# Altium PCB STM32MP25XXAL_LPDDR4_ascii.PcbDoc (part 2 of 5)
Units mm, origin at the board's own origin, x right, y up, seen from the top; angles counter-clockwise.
Board outline 125 x 95 mm, 6 copper layers (Top Layer, Signal Layer 1, Signal Layer 2, Signal Layer 3, Signal Layer 4, Bottom Layer), stack 1.403 mm thick; 182 components, 297 nets, 1131 pads, 958 vias.
Unrouted connection lines stored in the file: 5.
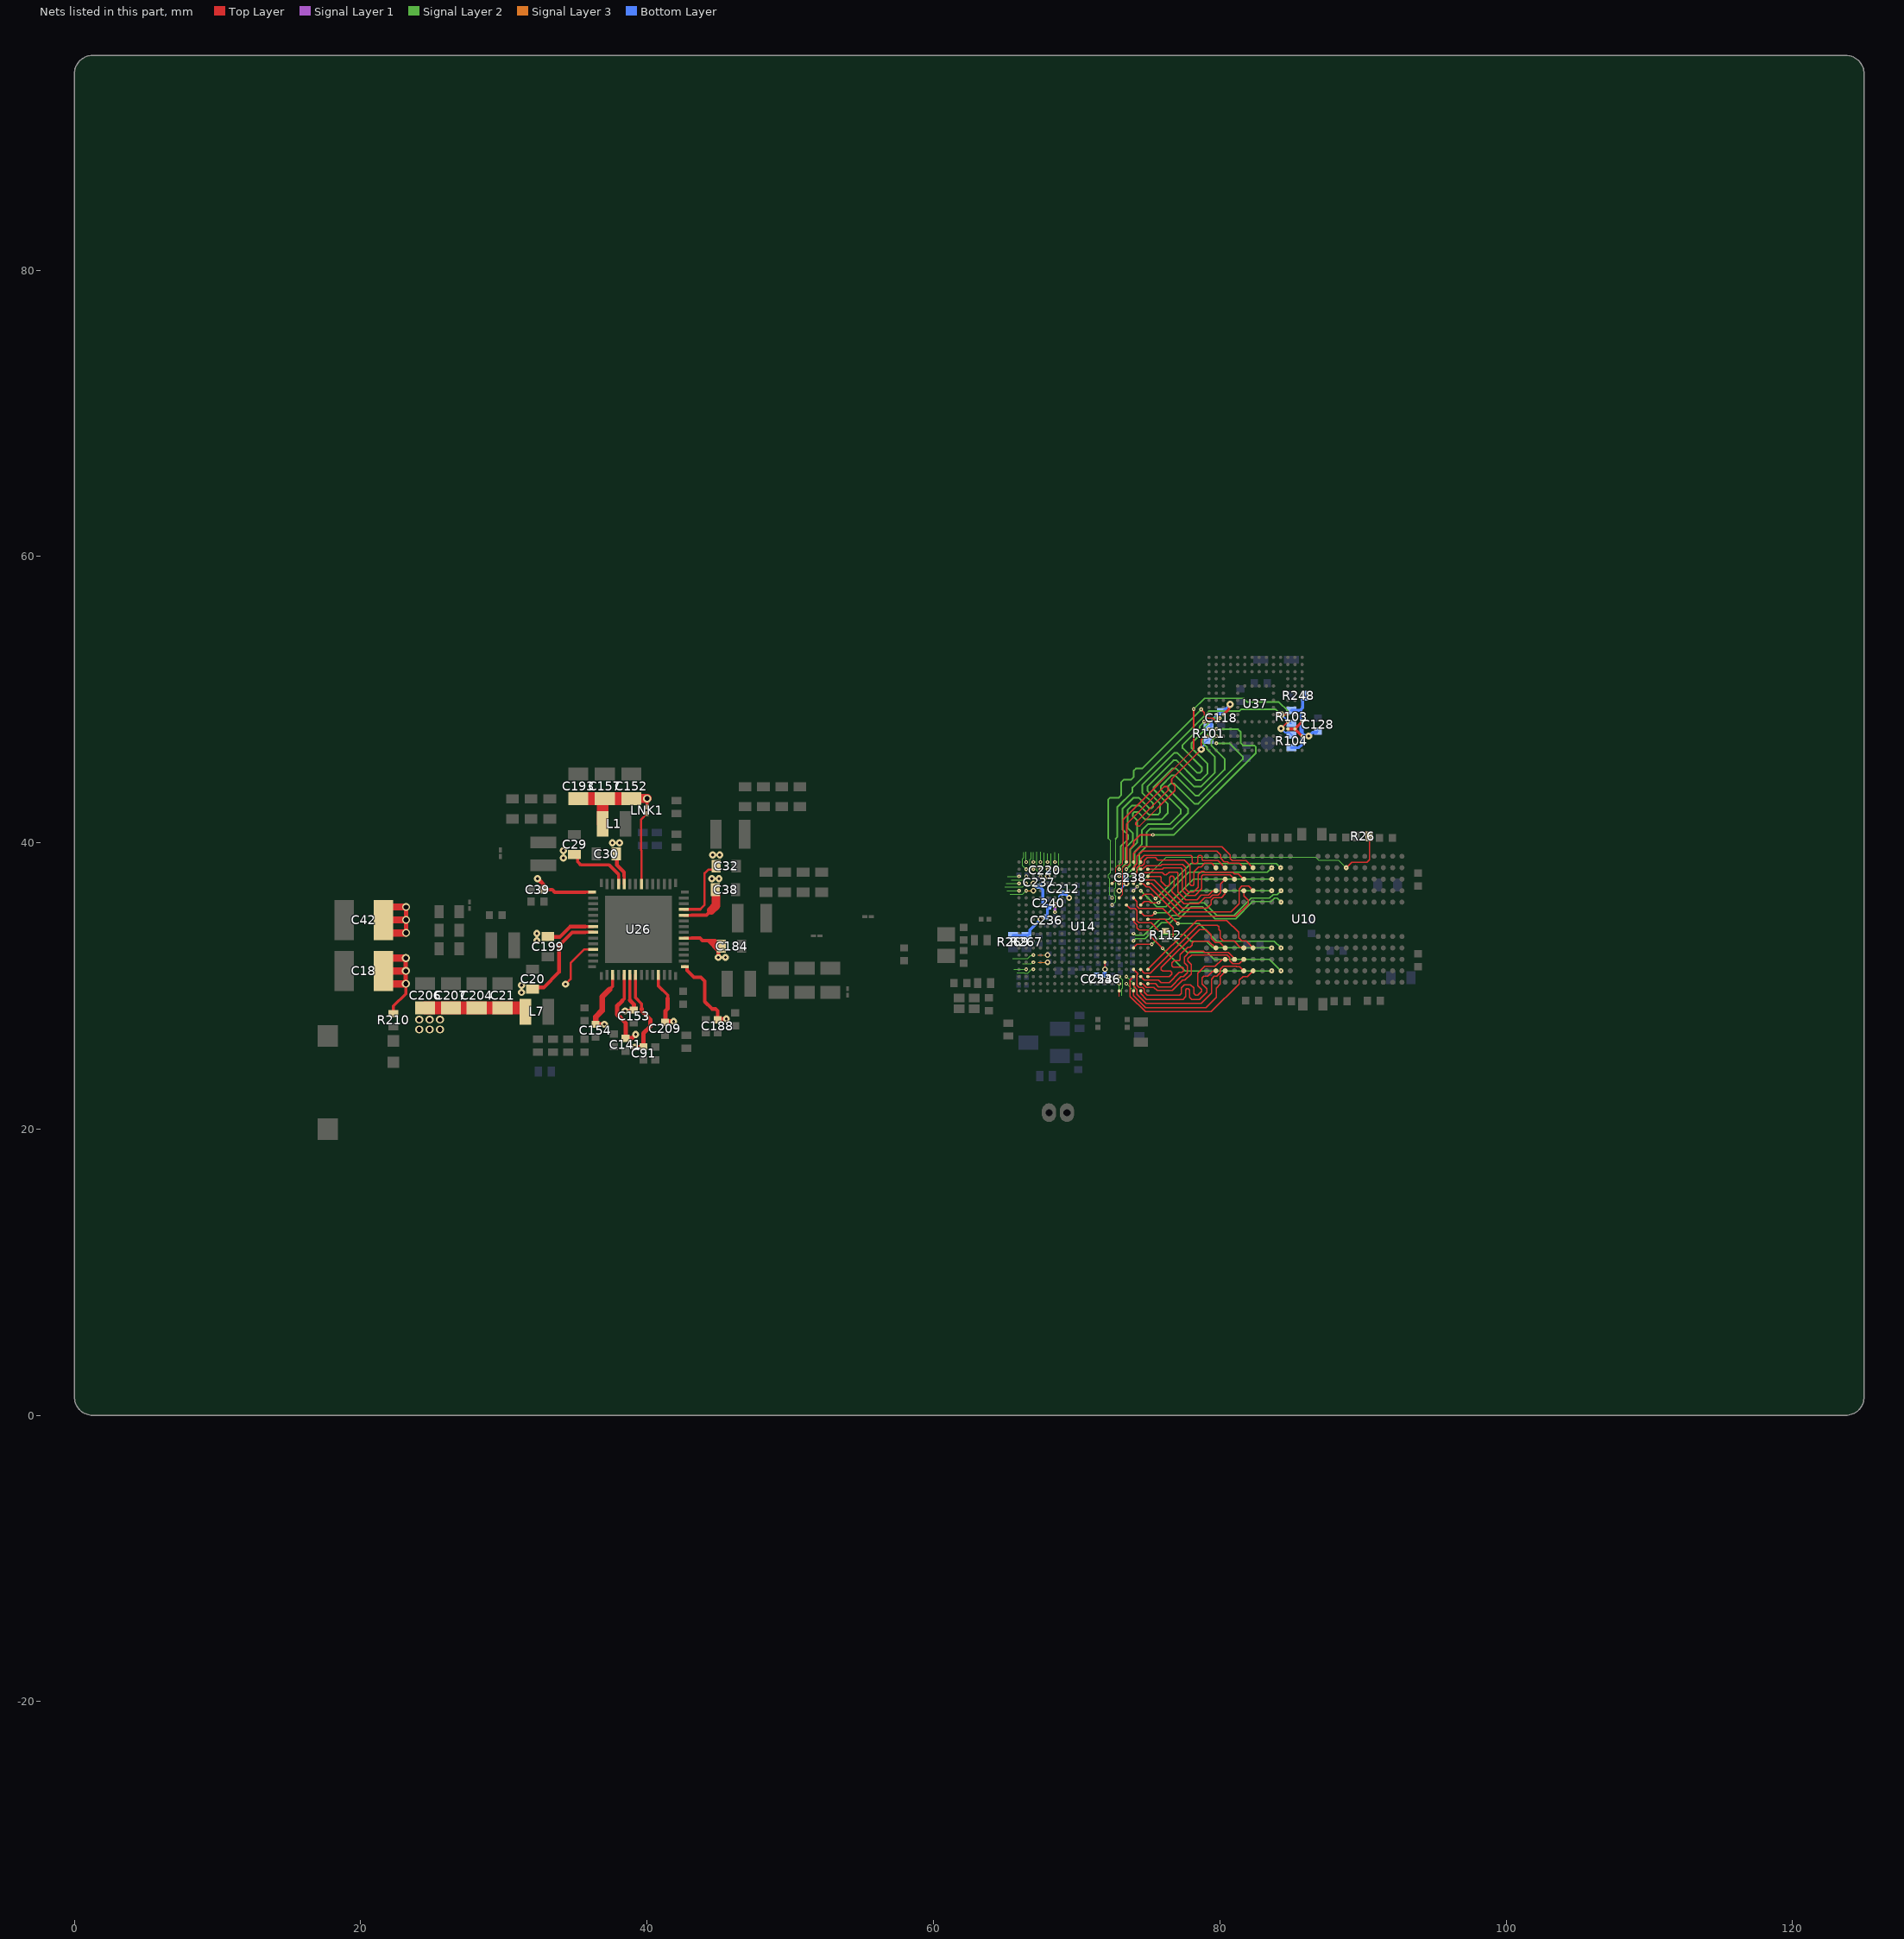
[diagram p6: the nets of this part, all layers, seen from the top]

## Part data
B2: library part MCD-03492, "Switch tactile, SPST-NO, 50mA, 12V, 6x3.8mm"
C1 C2 C3 C4 C5 C15 C214 C250 C260: library part MCD-02377, "Capacitor, MLCC, 1uF, 6.3V, X5R, +/-20%, 0201, T=0,3mm"
C9 C52 C53 C54 C55 C56 C57 C58 C59 C60 C61 C64 C65 C66 C67 C68 C87 C118 C130: library part MCD-00006, "Capacitor, MLCC, 100nF, 16V, X7R, +/-10%, 0402, T=0.5mm"
C14: library part MCD-01823, "Capacitor, MLCC, 2.2uF, 6V3, X5R,+/-10%, 0402, T=0.5mm"
C16 C17 C201 C210 C212 C215 C219 C220 C234 C236 C237 C238 C240 C244 C246 C248 C251 C253: library part MCD-01535, "Capacitor, MLCC,100nF, 10V, X5R, +/-10%, 0201, T=0.3mm"
C18 C42: library part MCD-01796, "Capacitor, Tantalum, 100uF, 6V3, 40mR, +/-20%,  Type_B (3528 metric), T=1.9mm"
C19 C21 C152 C157 C186 C187 C193 C204 C206 C207: library part MCD-03139, "Capacitor, MLCC, 22uF, 10V, X5R, +/-20%, 0805, T=1,25mm"
C20 C29 C30 C32 C38 C184 C199: library part MCD-00099, "Capacitor, MLCC, 10uF, 10V, X5R, +/-10%, 0603, T=0,8mm"
C22 C23 C24 C26 C27 C28 C34 C35 C36 C37 C41 C183 C200 C202: library part MCD-00100, "Capacitor, MLCC, 22uF, 6V3, X5R, +/-20%, 0603, T=0,8mm"
C33: library part MCD-00011, "Capacitor, MLCC, 10nF, 16V, X7R, +/-10%, 0402, T=0.5mm"
C39 C43 C153 C154 C188: library part MCD-00095, "Capacitor, MLCC, 1uF, 25V, X5R, +/-10%, 0402, T=0.5mm"
C40: library part MCD-03140, "Capacitor, MLCC, 10uF, 6.3V, X5R, +/-20%, 0402, T=0.5mm"
C50 C51 C62 C63: library part MCD-01341, "Capacitor, MLCC, 10uF, 6V3, X5R, +/-20%, 0603, T=0.8mm"
C79 C117 C128: library part MCD-02606, "Capacitor, MLCC, 2.2uF, 6.3V, X5R, +/-10%, 0402, T=0.5mm"
C81 C86 C90 C92: library part MCD-00674, "Capacitor, MLCC, 6.8pF, 50V, NPO, +/-0.25pF, 0402, T=0.5mm"
C91 C141 C142 C156 C189 C190 C208 C209 C217: library part MCD-01356, "Capacitor, MLCC, 4.7uF, 6V3, X5R, +/-20%, 0402, T=0.5mm"
C155: library part MCD-02198, "Capacitor, MLCC, 10nF, 50V, X7R, +/-10%, 0402, T=0.5mm"
C175 C177 C191 C192 C194 C195 C196 C197 C203 C205 C211 C213 C283 C284 C287 C289 C299 C300 C304 C306 C307: library part MCD-01533, "Capacitor, MLCC, 1uF, 6V3, X5R, +/-20%, 0201, T=0.3mm"
C225: library part MCD-01534, "Capacitor, MLCC, 4,7uF, 6V3, X5R, +/-20%, 0201, T=0.5mm"
C235: library part MCD-02235, "Capacitor, MLCC, 2.2uF, 10V, X5R,+/-10%, 0201, T=0.5mm"
CN12: library part MCD-00655, "Header, 2x1, 1.25mm, VR, TH, T=2.25mm/2.3mm"
D6: library part MCD-03280, "Diode, Schottky, Dual Common Cathode, 0V3, 300mA, 40V, SOT-23"
D7: library part MCD-00034, "Diode, Schottky, 0V53, 1A, 10V, SOD323"
L1 L6: library part MCD-03143, "Inductor, 2.2uH, +/-20%, Itemp= 1700mA, Isat= 2400mA, 0R140, 0806, T=1mm"
L2 L4: library part MCD-03142, "Inductor, 0.68uH, +/-20%, Itemp= 3900mA, Isat= 5400mA, 0R031, 1008, T=1.2mm"
L3 L5 L7: library part MCD-03141, "Inductor, 0.68uH, +/-20%, Itemp= 3100mA, Isat= 4300mA, 0R043, 0806, T=1mm"
LD11: library part MCD-00588, "LED Green, 0603 SMD, Forward Voltage Typ=2V, Max=2.5V"
LNK1 LNK2 LNK4 LNK7 LNK8 LNK11: library part MCD-02777, "Track link on PCB 200um width for layout routing"
R2 R46 R57 R59 R60 R81: library part MCD-00052, "Resistor,0R,0402,5%,1/16W"
R3 R64 R67 R267 R269 R286: library part MCD-00052, "Resistor, 0R, 0402, +/-5%, 1/16W"
R11: library part MCD-00056, "Resistor, 0R, 0603, +/-5%, 1/10W"
R26 R27 R101 R103 R104 R248 R272: library part MCD-00053, "Resistor, 10K, 0402, +/-1%, 1/16W"
R66: library part MCD-00058, "Resistor, 20R, 0402, +/-1%, 1/16W"
R94 R112: library part MCD-02253, "Resistor, 240R, 0201, +/-1%, 1/20W"
R210: library part MCD-00441, "Resistor,270R,0402,1%,1/16W"
R260 R261: library part MCD-00068, "Resistor, 1K5, 0402, +/-1%, 1/16W"
TP21: library part MCD-00074, "Test Point, SMD, 1mm"
U10: library part MCD-04012, "Memory, SDRAM, 1V1, 16Gbit, 4266Mhz"
U14: library part MCD-03768, "MPU, dual core ARM cortex-A35 64-bit + M33 32-bit, 808KB SRAM, With Crypto"
U26: library part MCD-03000, "STPMIC2"
U37: library part MCD-02799, "Memory, eMMC, 3V3, 4Gbit, 52MHz"
X1: library part MCD-01479, "Crystal, 32.768kHz, 6pF, +/-20ppm, 80K, 2.05x1.2mm"
X2: library part MCD-02344, "Crystal, 40MHz, 6pF, +/-20ppm, 80R, 1.6x1.2mm"

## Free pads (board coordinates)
  round 0.508 on Mech21: 1(39.085,-32.513)
  round 0.508 on Mech20: 1(87.94,-32.521)

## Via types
v1: diameter 0.26, hole 0.1, Top Layer to Signal Layer 1, 266 vias
v2: diameter 0.5, hole 0.2, Top Layer to Bottom Layer, 216 vias
v3: diameter 0.26, hole 0.1, Signal Layer 1 to Signal Layer 2, 138 vias
v4: diameter 0.4, hole 0.2, Signal Layer 1 to Signal Layer 4, 99 vias
v5: diameter 0.4, hole 0.2, Top Layer to Bottom Layer, tented both sides, 94 vias
v6: diameter 0.26, hole 0.1, Signal Layer 4 to Bottom Layer, 82 vias
v7: diameter 0.55, hole 0.35, Top Layer to Bottom Layer, 55 vias
v8: diameter 0.55, hole 0.3, Top Layer to Bottom Layer, 7 vias
v9: diameter 0.5, hole 0.2, Signal Layer 1 to Signal Layer 4, 1 vias

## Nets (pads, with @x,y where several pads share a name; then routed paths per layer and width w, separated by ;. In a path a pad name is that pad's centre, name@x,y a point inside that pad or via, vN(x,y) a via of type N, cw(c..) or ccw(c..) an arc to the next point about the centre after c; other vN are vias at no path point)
1V8: C118.2 C128.2 C152.2 C157.2 C193.2 C212.2 C220.2 C236.2 C237.2 C238.2 C240.2 C246.2 C253.2 L1.2 LNK1.2 R101.2 R103.2 R104.2 R248.2 R267.2 R269.1 U14.C5 U14.D3 U14.D16 U14.E15 U14.F8 U14.G6 U14.H6 U14.J4 U14.R13 U14.T13 U37.C6 U37.M4 U37.N4 U37.P3 U37.P5 | length 31.6
  Top Layer w0.1: U14.R13@71.975,31.65 v6(71.975,31.15) 71.975,31.125 U14.T13@72,31.1
  Top Layer w0.15: U37.P3@85.751,47.447 85.753,47.449 86.224,47.449 v2@86.225,47.45
  Top Layer w0.2: LNK1.2@39.998,42.487 v7(39.998,43.089) ; U37.C6@80.25,48.95 80.647,49.347 80.647,49.582 v2(80.725,49.66) ; U37.M4@84.751,47.947 U37.N4@85.251,47.947 ; U37.P3@85.751,47.447 U37.N4@85.251,47.947 ; U37.P5@85.751,48.447 U37.N4@85.251,47.947
  Top Layer w0.64: C152.2@38.898,43.089 v7(39.998,43.089)
  Top Layer w0.8: L1.2@36.893,41.314 36.893,43.039 36.943,43.089 C157.2@37.048,43.089
  Top Layer w0.9: C193.2@35.198,43.089 C157.2@36.943,43.089 ; C157.2@37.048,43.089 C152.2@38.898,43.089
  Signal Layer 1 w0.2: v1(68.475,35.15) v4(68.475,35.65)
  Bottom Layer w0.1: C237.2@67.38,36.95 67.717,37.287 67.717,37.392 v4(67.975,37.65) ; v4(68.475,35.65) 68.475,35.693 68.538,35.756 68.538,35.783 68.755,36.001 68.755,36.271 68.834,36.35 68.925,36.35 C212.2@69.05,36.475 ; v1(72.975,36.65) v6(73.475,37.15) 73.475,37.535 C238.2@73.45,37.56 ; C128.2@86.754,47.704 C128.2@86.85,47.8
  Bottom Layer w0.2: R269.1@65.55,33.5 65.575,33.525 66.597,33.525 66.727,33.655 66.727,33.902 v6(67.475,34.65) ; v4(66.975,37.15) 67.2,36.925 C237.2@67.4,36.925 ; C237.2@67.4,36.93 67.455,36.875 67.475,36.875 67.635,36.715 67.635,35.796 67.856,35.575 67.97,35.575 C240.2@68.045,35.5 67.97,35.425 67.97,35.319 67.959,35.308 67.959,35.017 67.955,35.013 67.955,34.9 67.705,34.65 v6@67.491,34.65 ; v4(67.975,37.65) 67.975,38.025 C220.2@68.05,38.1 ; C240.2@68.113,35.568 v6@68.377,35.568 ; C212.2@69.1,36.4 69.225,36.4 v4(69.475,36.15) ; C253.2@71.333,30.745 71.336,30.748 71.948,30.748 C246.2@71.95,30.745 ; v6@71.95,31.125 v6(71.975,31.15) ; C246.2@71.975,30.745 v6@71.975,31.125 ; R101.2@79.211,48.058 79.261,48.058 79.416,48.213 79.416,48.505 79.916,49.006 79.916,49.008 80.071,49.163 C118.2@80.096,49.163 ; C118.2@80.175,49.11 80.715,49.65 v2@80.75,49.65 ; R103.2@85.007,49.244 85.605,49.244 ; R104.2@85.011,46.638 85.526,46.638 85.721,46.833 85.721,47.282 85.897,47.458 ; 85.703,48.212 85.676,48.239 85.676,49.174 85.605,49.244 ; R248.2@85.943,50.263 85.788,50.108 85.788,49.428 85.605,49.244 ; v2@86.225,47.45 86.479,47.704 C128.2@86.754,47.704
  Bottom Layer w0.3: 85.703,48.212 85.703,47.651 85.897,47.458 86.217,47.458 v2@86.225,47.45
  other v1: 71.975,31.15 67.475,34.65 68.475,35.65 69.475,36.15 66.975,37.15 73.475,37.15 67.975,37.65
  other v2: 86.215,47.45
  other v4: 71.975,31.15 67.475,34.65 72.975,36.65 73.475,37.15
  other v6: 68.475,35.65 69.475,36.15 72.975,36.65 66.975,37.15 67.975,37.65
1V8_FB: LNK1.1 U26.35 | length 5.1
  Top Layer w0.15: U26.35@39.598,37.109 39.598,39.45 39.573,39.475 39.573,41.612 LNK1.1@39.998,42.037
3V3: C21.2 C154.2 C204.2 C206.2 C207.2 L7.2 U26.3 U26.53 | length 15.3
  Top Layer w0.15: v2(34.308,30.116) 34.66,30.468 34.66,31.604 35.595,32.539 U26.53@36.228,32.539 ; U26.53@36.018,32.508 36.317,32.508 U26.53@36.348,32.539
  Top Layer w0.21: 37.371,29.736 37.598,29.964 U26.3@37.598,30.769
  Top Layer w0.3: C154.2@36.373,27.314 C154.2@36.398,27.314 v2@36.983,27.314
  Top Layer w0.4: C154.2@36.398,27.314 36.412,27.328 36.412,27.824 36.858,28.27 36.858,29.224 37.371,29.736
  Top Layer w0.9: C206.2@24.485,28.462 C21.2@29.898,28.462 31.26,28.462 L7.2@31.285,28.437
  other v2: 37.008,27.314
  other v7: 24.085,26.962 24.81,26.962 25.535,26.962 24.085,27.637 24.81,27.637 25.535,27.637
5V_HDMI: C91.1 U26.7 | length 6.1
  Top Layer w0.21: U26.7@39.198,30.769 39.198,29.164 39.613,28.749 39.613,28.392
  Top Layer w0.3: v2(39.138,25.719) C91.1@39.748,25.719 ; 39.613,28.392 39.613,28.257 40.233,27.637 40.233,27.174 39.748,26.689 C91.1@39.748,25.869
5V_STLK: C18.1 C20.2 C29.2 C30.2 C32.2 C38.2 C39.2 C42.1 C153.2 C184.2 C188.2 C199.2 C209.2 R210.1 U26.6 U26.11 U26.15 U26.20 U26.24 U26.25 U26.38 U26.39 U26.43 U26.49 U26.50 | length 63.3
  Top Layer w0.15: 43.698,35.339 44.023,35.664 44.023,37.87 44.286,38.133 44.717,38.133 C32.2@44.823,38.239
  Top Layer w0.2: R210.1@22.284,28.054 22.284,28.588 23.142,29.446 v7@23.142,30.133
  Top Layer w0.21: C29.2@34.923,39.189 35.16,38.952 35.16,38.652 35.373,38.439 37.362,38.439 37.998,37.803 U26.39@37.998,37.109 ; 35.673,33.739 U26.50@36.228,33.739 ; 35.673,34.139 U26.49@36.228,34.139 ; 35.673,36.539 U26.43@36.228,36.539 ; U26.38@38.398,37.109 38.398,37.664 ; 38.798,28.989 U26.6@38.798,30.769 ; U26.11@40.798,30.769 40.798,29.982 41.438,29.342 41.438,29.114 ; U26.15@42.568,31.339 U26.15@42.643,31.339 U26.15@42.683,31.339 ; U26.20@42.568,33.339 43.123,33.339 ; U26.24@42.568,34.939 43.105,34.939 ; U26.25@42.568,35.339 43.698,35.339
  Top Layer w0.25: C20.2@31.998,29.889 32.773,29.889 33.848,30.964 33.848,32.808 34.779,33.739 35.673,33.739 ; 32.593,37.264 32.597,37.264 32.743,37.118 32.743,36.824 C39.2@32.853,36.714 ; C39.2@32.903,36.714 33.373,36.714 33.548,36.539 35.673,36.539 ; C199.2@33.073,33.414 33.889,33.414 34.614,34.139 35.673,34.139 ; C30.2@37.823,39.214 37.892,39.145 37.892,38.447 38.398,37.941 38.398,37.664 ; 42.793,31.234 42.793,31.086 43.269,30.611 43.751,30.611 44.023,30.339 44.023,28.898 44.532,28.389 44.777,28.389 44.923,28.243 C188.2@44.923,27.689 ; 43.105,34.939 44.148,34.939 44.473,35.264 ; 43.123,33.339 43.686,33.339 43.861,33.164 44.256,33.164 ; v2(44.973,31.989) 44.973,32.447 44.256,33.164 ; 44.256,33.164 44.477,33.164 ; 44.477,33.164 44.875,32.766 45.144,32.766 45.145,32.764 45.145,32.842 44.948,33.039 44.87,33.039 44.745,33.164 44.477,33.164
  Top Layer w0.3: v7@23.148,30.139 23.148,31.045 v7@23.148,31.939 ; v7@23.173,33.702 v7@23.173,35.502 ; v2@32.342,37.515 32.593,37.264 ; v2(38.463,28.249) 39.073,28.249 39.072,28.25 39.072,28.715 38.798,28.989 ; C209.2@41.248,27.519 C209.2@41.273,27.519 ; 41.438,29.114 41.438,28.408 41.273,28.243 C209.2@41.273,27.519 ; v2(41.858,27.519) C209.2@41.273,27.519 ; C188.2@44.923,27.689 v2(45.533,27.689)
  Top Layer w0.5: C18.1@21.584,30.133 23.142,30.133 v7@23.167,30.133 ; C18.1@21.584,31.045 23.148,31.045 v7@23.167,31.045 ; C18.1@21.584,31.945 v7@23.167,31.945 ; C42.1@21.584,33.696 v7@23.167,33.696 ; C42.1@21.584,34.607 v7@23.167,34.607 ; C42.1@21.584,35.507 v7@23.167,35.507
  Top Layer w0.6: 44.473,35.264 44.798,35.589 C38.2@44.798,36.314
  other v2: 31.223,29.539 31.223,30.039 45.473,31.989 32.298,33.164 32.298,33.664 32.348,37.487 44.523,37.489 45.023,37.489 34.148,38.939 44.573,39.139 45.073,39.139 34.148,39.439 37.573,39.989 38.073,39.989
  other v7: 23.149,30.141 23.149,31.041 23.149,31.941 23.174,33.704 23.174,34.604 23.174,35.504
5V_VCONN: C141.1 U26.5 | length 5.7
  Top Layer w0.21: 38.276,28.966 38.398,29.089 U26.5@38.398,30.769
  Top Layer w0.3: 38.276,28.966 37.908,28.599 37.908,28.004 38.498,27.414 C141.1@38.498,26.339 38.938,26.339 v2(39.198,26.599)
ANA0: U14.R5 | length 0.7
  Signal Layer 3 w0.075: 67.3,31.65 v4(67.975,31.65)
  other v1: 67.975,31.65
ANA1: U14.P5 | length 0.7
  Signal Layer 3 w0.075: 67.275,32.15 v4(67.975,32.15)
  other v1: 67.975,32.15
BOOT0: U14.T2 | length 0.9
  Signal Layer 2 w0.075: 65.625,31.15 v3(66.475,31.15)
  other v1: 66.475,31.15
BOOT1: U14.P3 | length 1.6
  Signal Layer 2 w0.075: 65.526,31.901 66.578,31.901 66.612,31.934 66.613,31.934 66.806,32.126 66.951,32.126 v3(66.975,32.15)
  other v1: 66.975,32.15
BOOT2: U14.T3 | length 1.3
  Signal Layer 2 w0.075: 65.822,30.925 66.347,30.925 66.372,30.901 66.578,30.901 66.724,31.047 66.724,31.05 66.804,31.129 66.954,31.129 v3(66.975,31.15)
  other v1: 66.975,31.15
BOOT3: U14.R3 | length 0.8
  Signal Layer 2 w0.075: 66.221,31.558 66.839,31.558 66.931,31.65 v3(66.975,31.65)
  other v1: 66.975,31.65
COMBOPHY_REXT: U14.W15 | length 0.4
  Top Layer w0.075: 72.975,29.25 U14.W15@72.975,29.65
COMBOPHY_RX1N: U14.V16 | length 0.5
  Signal Layer 2 w0.075: v3(73.475,30.15) 73.819,29.806 73.819,29.763
  other v1: 73.475,30.15
COMBOPHY_RX1P: U14.U16 | length 1.3
  Signal Layer 2 w0.075: v3(73.475,30.65) 74.017,30.108 74.017,29.617
  other v1: 73.475,30.65
COMBOPHY_TX1N: U14.V15 | length 0.8
  Signal Layer 2 w0.075: 72.975,29.325 v3(72.975,30.15)
  other v1: 72.975,30.15
COMBOPHY_TX1P: U14.U15 | length 1.5
  Signal Layer 2 w0.075: v3(72.975,30.65) 73.224,30.401 73.224,29.874 73.15,29.8 73.15,29.325
  other v1: 72.975,30.65
CSI_CKN: U14.C2 | length 1.2
  Signal Layer 2 w0.075: 65.425,37.4 65.426,37.399 66.224,37.399 v3(66.475,37.65)
  other v1: 66.475,37.65
CSI_CKP: U14.C1 | length 0.8
  Signal Layer 2 w0.075: 65.175,37.65 65.973,37.65 v3(65.975,37.648)
  other v1: 65.975,37.648
CSI_D0N: U14.E1 | length 0.8
  Signal Layer 2 w0.075: 65.15,36.65 v3(65.975,36.65)
  other v1: 65.975,36.65
CSI_D0P: U14.E2 | length 1.2
  Signal Layer 2 w0.075: 65.35,36.4 66.225,36.4 v3(66.475,36.65)
  other v1: 66.475,36.65
CSI_D1N: U14.D2 | length 1.6
  Signal Layer 2 w0.075: 64.982,36.9 66.225,36.9 v3(66.475,37.15)
  other v1: 66.475,37.15
CSI_D1P: U14.D1 | length 0.9
  Signal Layer 2 w0.075: 65.076,37.149 v3(65.975,37.149)
  other v1: 65.975,37.149
CSI_REXT: U14.E3 | length 0.6
  Signal Layer 3 w0.075: 66.4,36.65 v1(66.975,36.65)
  other v4: 66.975,36.65
DDR_CA0: U10.H2 U14.J17 | length 11.6
  Top Layer w0.09: U14.J17@73.975,34.65 73.993,34.632 73.993,34.486 74.225,34.254 74.225,34.046 74.371,33.9 75.092,33.9 75.233,33.759 75.233,33.392 v3(76,32.625)
  Signal Layer 2 w0.09: v3(76,32.625) 77.595,31.03 83.605,31.03 v1(83.625,31.05) v3@83.65,31.075
  other v1: 76,32.625
  other v3: 83.625,31.05
DDR_CA1: U10.J2 U14.J19 | length 11.3
  Top Layer w0.09: U14.J19@74.975,34.65 76.175,34.65 76.75,34.075 76.75,33.35 v3(76.725,33.325)
  Signal Layer 2 w0.09: v3(76.725,33.325) 77.728,32.322 79.134,32.322 79.606,31.85 83.475,31.85 v1(84.275,31.05)
  other v1: 76.725,33.325
  other v3: 84.275,31.05
DDR_CA2: U10.H9 U14.H18 | length 10
  Top Layer w0.09: U14.H18@74.475,35.15 74.725,34.9 75.275,34.9 v3(75.475,35.1)
  Signal Layer 2 w0.09: v3(75.475,35.1) 76.426,35.1 77.976,36.65 v1(83.625,36.65)
  other v1: 75.475,35.1
  other v3: 83.625,36.65
DDR_CA3: U10.H10 U14.E18 | length 10.4
  Signal Layer 2 w0.09: v3@74.475,36.643 75.593,35.525 76.24,35.525 78.165,37.45 v3(83.625,37.45)
  other v1: 74.475,36.65 83.625,37.45
  other v3: 74.475,36.65
DDR_CA4: U10.H11 U14.G18 | length 10.3
  Top Layer w0.09: U14.G18@74.475,35.65 74.725,35.9 75.075,35.9 ; 75.079,35.9 75.172,35.806 75.716,35.806 v3(75.725,35.815)
  Signal Layer 2 w0.09: v3(75.725,35.815) 77.835,37.925 83.3,37.925 v1(83.625,38.25)
  other v1: 75.725,35.815
  other v3: 83.625,38.25
DDR_CA5: U10.J11 U14.F18 | length 11.1
  Top Layer w0.09: U14.F18@74.475,36.112 U14.F18@74.475,36.15 74.725,36.4 75.2,36.4 v1(75.5,36.1)
  Signal Layer 2 w0.09: v3@75.525,36.1 77.965,38.54 83.96,38.54 v1(84.25,38.25)
  other v3: 75.5,36.1 84.25,38.25
DDR_CKE: U10.J4 U14.F17 | length 12
  Top Layer w0.09: U14.F17@73.975,36.15 74.225,35.9 74.225,35.546 74.371,35.4 76.025,35.4 v3(77.075,34.35)
  Signal Layer 2 w0.09: v3(77.075,34.35) 78.55,34.35 79.775,33.125 ; 79.775,33.12 83.805,33.12 v1(84.275,32.65)
  other v1: 77.075,34.35
  other v3: 84.275,32.65
DDR_CLK_N: U10.J9 U14.L17 | length 12.4
  Signal Layer 2 w0.09: v1(73.975,33.65) 73.999,33.65 74.113,33.536 74.686,33.536 75.812,34.662 76.434,34.662 76.696,34.925 77.05,34.925 77.917,35.792 78.906,35.792 79.773,34.925 81,34.925 82.2,36.125 83.475,36.125 83.724,36.374 84.012,36.374 84.275,36.637 v1(84.275,36.65)
  other v3: 73.975,33.65 84.275,36.65
DDR_CLK_P: U10.J8 U14.M17 | length 12.4
  Signal Layer 2 w0.09: v1(73.975,33.15) 74.113,33.286 74.79,33.286 75.916,34.412 76.537,34.412 76.8,34.675 77.154,34.675 78.021,35.542 78.802,35.542 79.67,34.675 81.104,34.675 82.304,35.875 83.579,35.875 83.828,36.124 84.016,36.124 84.275,35.866 v1(84.275,35.85)
  other v3: 73.975,33.15 84.275,35.85
DDR_CS: U10.H4 U14.N17 | length 10.5
  Top Layer w0.09: U14.N17@73.975,32.65 74.225,32.9 v3(75.25,32.9)
  Signal Layer 2 w0.09: v3@75.25,32.875 75.989,33.614 77.486,33.614 77.975,33.125 79.05,33.125 79.525,32.65 v1(83.625,32.65)
  other v1: 75.25,32.9
  other v3: 83.625,32.65
DDR_DQ0: U10.B2 U14.W18 | length 8.6
  Top Layer w0.09: 74.478,29.465 U14.W18@74.478,29.647 ; 74.483,29.462 74.886,29.06 77.435,29.06 77.6,29.225 ; 77.605,29.236 77.605,29.717 77.684,29.796 77.8,29.796 77.895,29.701 77.895,29.205 78.04,29.06 78.575,29.06 79.083,29.567 ; 79.085,29.565 79.085,29.801 78.765,30.122 78.765,30.565 78.889,30.689 79.164,30.689 79.496,31.021 79.695,31.021 U10.B2@79.725,31.05
DDR_DQ1: U10.C2 U14.W17 | length 8.9
  Top Layer w0.09: 73.975,29.325 U14.W17@73.975,29.65 ; 73.978,29.324 74.821,28.48 79.039,28.48 79.744,29.185 ; 79.745,29.185 79.745,29.832 80.035,30.122 80.035,30.647 80.381,30.993 U10.C2@80.381,31.044
DDR_DQ2: U10.E2 U14.V17 | length 10.5
  Top Layer w0.09: U14.V17@73.989,30.136 73.989,29.99 74.225,29.754 74.225,29.385 ; 74.227,29.385 74.841,28.77 78.7,28.77 79.417,29.486 ; 79.415,29.486 79.415,30.471 79.619,30.675 79.788,30.675 80.035,30.922 80.035,31.149 80.246,31.36 81.153,31.36 81.188,31.325 81.4,31.325 U10.E2@81.675,31.05
DDR_DQ3: U10.F2 U14.U17 | length 11.8
  Top Layer w0.09: U14.U17@73.975,30.65 73.732,30.407 73.732,29.268 74.809,28.191 74.811,28.191 ; 74.811,28.19 79.407,28.19 81.349,30.133 ; 81.357,30.144 81.357,30.391 ; 81.358,30.39 81.612,30.644 81.914,30.644 U10.F2@82.32,31.05
DDR_DQ4: U10.F4 U14.T19 | length 9.8
  Top Layer w0.09: U14.T19@74.975,31.15 78.4,34.575 80.49,34.575 81.32,33.746 81.32,33.692 ; 81.335,33.692 81.335,33.352 81.546,33.14 81.835,33.14 U10.F4@82.325,32.65
DDR_DQ5: U10.E4 U14.T18 | length 9.8
  Top Layer w0.09: U14.T18@74.475,31.15 74.725,30.9 75.135,30.9 78.48,34.245 79.83,34.245 79.945,34.13 79.945,33.938 80.035,33.848 80.035,33.352 80.246,33.14 80.983,33.14 81.423,32.7 81.625,32.7 U10.E4@81.675,32.65
DDR_DQ6: U10.C4 U14.U19 | length 9.1
  Top Layer w0.09: U14.U19@74.975,30.65 76.486,30.65 76.655,30.82 76.655,30.93 76.562,31.023 76.026,31.023 75.91,31.139 75.91,31.265 78.59,33.945 ; 78.592,33.942 79.021,33.942 79.39,33.573 79.39,33.32 79.685,33.025 80.002,33.025 U10.C4@80.375,32.652
DDR_DQ7: U10.B4 U14.U18 | length 9
  Top Layer w0.09: U14.U18@74.475,30.65 74.725,30.4 75.727,30.4 75.912,30.215 76.461,30.215 77.178,30.932 77.337,30.932 77.455,31.05 77.455,31.223 77.361,31.317 76.745,31.317 76.651,31.411 76.651,31.596 76.808,31.752 77.151,31.752 77.235,31.836 77.235,32.18 77.755,32.7 77.925,32.7 78.065,32.84 78.065,33.01 78.182,33.127 79.222,33.127 79.699,32.65 U10.B4@79.725,32.65
DDR_DQ8: U10.B11 U14.C17 | length 9.5
  Top Layer w0.09: U14.C17@73.975,37.65 74.225,37.9 74.225,38.254 74.371,38.4 74.579,38.4 74.725,38.546 74.725,38.754 74.921,38.95 75.5,38.95 75.67,38.78 77.517,38.78 77.915,38.382 77.915,37.089 78.001,37.003 78.124,37.003 78.205,37.083 78.205,37.971 78.534,38.301 78.685,38.301 78.688,38.304 ; 78.689,38.303 78.946,38.56 79.415,38.56 U10.B11@79.725,38.25
DDR_DQ9: U10.C11 U14.A18 | length 7.7
  Top Layer w0.09: U14.A18@74.475,38.65 74.475,38.88 74.725,39.13 77.978,39.13 78.079,39.028 78.079,38.631 78.182,38.529 78.35,38.529 78.463,38.641 78.463,39.038 78.552,39.128 78.667,39.128 78.75,39.045 78.75,38.815 78.825,38.74 79.885,38.74 80,38.625 U10.C11@80.375,38.25 U10.C11@80.376,38.249
DDR_DQ10: U10.E11 U14.B17 | length 9.2
  Top Layer w0.09: U14.B17@73.975,38.15 73.975,38.285 74.225,38.535 74.225,39.05 74.595,39.42 79.798,39.42 80.065,39.153 80.065,38.922 80.311,38.675 80.53,38.675 80.644,38.56 81.365,38.56 U10.E11@81.676,38.249
DDR_DQ11: U10.F11 U14.A17 | length 9.9
  Top Layer w0.09: U14.A17@73.975,38.65 73.975,39.225 74.46,39.71 80.153,39.71 80.715,39.149 80.715,38.904 80.879,38.74 81.835,38.74 U10.F11@82.325,38.25
DDR_DQ12: U10.F9 U14.D19 | length 9.7
  Top Layer w0.09: U14.D19@74.975,37.15 75.25,37.15 77.245,35.155 80.768,35.155 81.365,35.752 81.365,36.779 81.546,36.96 81.65,36.96 82.015,36.96 U10.F9@82.325,36.65 U10.F9@82.326,36.649
DDR_DQ13: U10.E9 U14.D18 | length 9.9
  Top Layer w0.09: U14.D18@74.475,37.15 U14.D18@74.496,37.129 ; U14.D18@74.49,37.123 74.648,37.123 74.871,36.9 75.09,36.9 77.125,34.865 81.128,34.865 81.985,35.722 81.985,35.979 81.675,36.289 U10.E9@81.675,36.65
DDR_DQ14: U10.C9 U14.D17 | length 8.1
  Top Layer w0.09: U14.D17@73.975,37.15 74.225,37.4 75.41,37.4 77.365,35.445 79.12,35.445 79.125,35.45 79.385,35.71 79.385,35.973 79.572,36.16 80.106,36.16 80.374,36.428 80.374,36.646 U10.C9@80.376,36.649
DDR_DQ15: U10.B9 U14.C18 | length 7.3
  Top Layer w0.09: U14.C18@74.48,37.65 74.73,37.9 76,37.9 76.15,37.75 76.265,37.75 ; 76.265,37.754 76.462,37.95 77.022,37.95 77.085,37.887 77.085,36.546 77.606,36.025 78.401,36.025 78.715,36.339 ; 78.715,36.34 79.203,36.34 79.49,36.627 79.701,36.627 U10.B9@79.725,36.65
DDR_DQM0: U10.C3 U14.T17 | length 11
  Top Layer w0.09: U14.T17@73.975,31.15 74.261,30.864 74.261,30.789 74.225,30.754 74.225,30.046 74.371,29.9 74.596,29.9 74.725,29.771 74.725,29.546 74.921,29.35 77.2,29.35 77.315,29.465 77.315,29.864 77.538,30.086 77.962,30.086 78.185,29.864 78.185,29.467 78.302,29.35 78.455,29.35 78.725,29.62 78.725,29.751 78.476,30.001 78.475,30.881 78.629,31.036 ; 78.625,31.04 78.946,31.36 79.673,31.36 80.14,31.827 80.351,31.827 U10.C3@80.375,31.85 ; U10.C3@80.38,31.844 U10.C3@80.395,31.858
DDR_DQM1: U10.C10 U14.C19 | length 9.1
  Top Layer w0.09: U14.C19@74.978,37.647 75.828,37.647 75.908,37.567 75.908,37.313 76.238,36.982 76.403,36.982 76.505,37.084 76.505,37.58 76.585,37.66 76.714,37.66 76.795,37.579 76.795,36.9 76.64,36.745 76.64,36.58 77.486,35.735 78.525,35.735 ; 78.523,35.737 78.946,36.16 79.317,36.16 79.497,36.34 79.881,36.34 80.056,36.515 80.056,37.129 U10.C10@80.376,37.449
DDR_DQS0_N: U10.E3 U14.V18 | length 9.9
  Top Layer w0.09: U14.V18@74.485,30.145 74.626,30.145 74.871,29.9 75.389,29.9 75.614,29.675 76.685,29.675 77.402,30.392 77.567,30.392 77.995,30.82 77.995,31.503 77.775,31.722 77.775,31.904 78.031,32.16 80.503,32.16 80.685,31.979 80.685,31.752 80.896,31.54 81.365,31.54 U10.E3@81.675,31.85
DDR_DQS0_P: U10.D3 U14.V19 | length 8.4
  Top Layer w0.09: U14.V19@74.975,30.15 75.04,30.15 75.492,30.15 75.717,29.925 76.581,29.925 77.298,30.642 77.464,30.642 77.745,30.923 77.745,31.399 77.525,31.619 77.525,32.007 77.928,32.41 78.862,32.41 78.865,32.41 78.935,32.34 80.605,32.34 81.025,31.92 U10.D3@81.025,31.85
DDR_DQS1_N: U10.E10 U14.B18 | length 10.4
  Top Layer w0.09: U14.B18@74.475,38.15 74.494,38.169 74.641,38.169 74.871,38.4 75.875,38.4 75.965,38.49 77.396,38.49 77.625,38.261 77.625,36.769 77.829,36.565 78.171,36.565 78.495,36.888 78.495,37.785 78.72,38.011 78.874,38.011 78.944,37.94 80.889,37.94 81.025,37.804 81.305,37.804 81.661,37.449 U10.E10@81.676,37.449 ; U10.E10@81.714,37.487 U10.E10@81.751,37.449
DDR_DQS1_P: U10.D10 U14.B19 | length 9
  Top Layer w0.09: U14.B19@74.975,38.15 75.979,38.15 76.069,38.24 77.293,38.24 77.375,38.158 77.375,36.666 77.726,36.315 78.275,36.315 78.745,36.785 78.745,37.679 78.819,37.753 ; 78.823,37.76 80.715,37.76 U10.D10@81.026,37.449
DDR_RESETN: R26.2 U10.T11 U14.E17 | length 19.8
  Top Layer w0.09: v1(88.825,38.25) 89.21,38.635 90.272,38.635 90.455,38.818 90.455,40.405 R26.2@90.425,40.435
  Top Layer w0.1: R26.2@90.22,40.64 R26.2@90.22,40.74
  Signal Layer 1 w0.1: v1(73.975,36.65) 73.975,36.675 74.175,36.875 v3@74.175,36.9
  Signal Layer 2 w0.075: v3@74.175,36.9 76.275,39 86.675,39 86.9,38.775 88.3,38.775 v1(88.825,38.25)
  other v3: 74.225,36.925 88.825,38.25
DDR_ZQ: R112.2 U14.G16 | length 3.9
  Top Layer w0.09: U14.G16@73.475,35.642 73.717,35.4 74.079,35.4 74.225,35.254 74.225,34.546 74.371,34.4 75.195,34.4 75.77,33.825 R112.2@76.2,33.825
DSI_CKN: U14.A4 | length 0.7
  Signal Layer 2 w0.075: v3(67.475,38.65) 67.475,39.35
  other v1: 67.475,38.65
DSI_CKP: U14.B4 | length 1.3
  Signal Layer 2 w0.075: v3(67.475,38.15) 67.725,38.4 67.725,39.3
  other v1: 67.475,38.15
DSI_D0N: U14.A5 | length 0.6
  Signal Layer 2 w0.075: v3(67.975,38.65) 67.975,39.25
  other v1: 67.975,38.65
DSI_D0P: U14.B5 | length 1.2
  Signal Layer 2 w0.075: v3(67.975,38.15) 68.225,38.4 68.225,39.225
  other v1: 67.975,38.15
DSI_D1N: U14.A6 | length 0.7
  Signal Layer 2 w0.075: v3(68.475,38.649) 68.48,38.654 68.48,39.32
  other v1: 68.475,38.649
DSI_D1P: U14.B6 | length 1.2
  Signal Layer 2 w0.075: v3(68.475,38.15) 68.75,38.425 68.75,39.25
  other v1: 68.475,38.15
DSI_D2N: U14.B3 | length 1.3
  Signal Layer 2 w0.075: 66.818,39.325 66.818,38.908 66.726,38.816 66.726,38.399 v3(66.975,38.15)
  other v1: 66.975,38.15
DSI_D2P: U14.A3 | length 0.7
  Signal Layer 2 w0.075: v3(66.975,38.65) 66.975,39.325
  other v1: 66.975,38.65
DSI_D3N: U14.B2 | length 1.3
  Signal Layer 2 w0.075: 66.318,39.325 66.318,38.968 66.226,38.876 66.226,38.399 v3(66.475,38.15)
  other v1: 66.475,38.15
DSI_D3P: U14.A2 | length 0.7
  Signal Layer 2 w0.075: v3(66.475,38.65) 66.475,39.35
  other v1: 66.475,38.65
DSI_REXT: U14.C4 | length 1.8
  Signal Layer 2 w0.075: 67.225,39.348 67.225,38.047 67.44,37.833 67.44,37.685 v3(67.475,37.65)
  other v1: 67.475,37.65
eMMC.SDMMC2_CK: R103.1 U14.G14 U37.M6 | length 23.1
  Top Layer w0.11: v2(84.275,48.95) 84.732,48.95 U37.M6@84.738,48.956
  Signal Layer 2 w0.075: v1(72.475,35.65) 72.725,35.899 72.725,36.253 72.65,36.328 72.65,36.785 72.726,36.86 72.726,40.275
  Signal Layer 2 w0.12: 72.726,40.275 72.833,40.383 72.833,42.475 73.9,43.542 73.9,43.85 79.237,49.187 81.362,49.187 81.5,49.325 83.9,49.325 v2(84.275,48.95)
  Bottom Layer w0.1: v2(84.275,48.95) 84.307,48.95 84.912,48.344 R103.1@85.007,48.344
  other v3: 72.475,35.65
eMMC.SDMMC2_CMD: R104.1 U14.D14 U37.M5 | length 24.2
  Top Layer w0.075: U14.D14@72.475,37.15 72.726,37.4 72.726,38.253 72.888,38.415 73.072,38.415 73.21,38.553 73.21,38.757 73.25,38.797
  Top Layer w0.1: 73.25,38.797 73.25,41.625 78.175,46.55 v1(78.175,49.325)
  Top Layer w0.11: v2@84.25,47.95 v1(84.75,48.45)
  Signal Layer 2 w0.11: v1(78.175,49.325) 78.939,50.089 81.661,50.089 81.925,49.825 84.127,49.825 84.75,49.202 v3@84.75,48.475
  Bottom Layer w0.11: v2@84.286,47.968 84.561,47.694 84.856,47.694 R104.1@85.011,47.538
  other v2: 84.276,47.977
  other v3: 84.75,48.45 78.175,49.325
eMMC.SDMMC2_D0: R101.1 U14.A16 U37.A3 | length 20
  Top Layer w0.1: U14.A16@73.5,38.675 73.5,41.309 76.112,43.92 76.305,43.92 76.4,43.825 76.4,43.674 74.133,41.407 74.133,41.267 74.225,41.175 74.408,41.175 76.866,43.633 76.866,43.959 76.637,44.188 76.637,44.446 v2(78.711,46.519) 78.711,47.201 78.956,47.447 U37.A3@79.251,47.447
  Bottom Layer w0.11: v2@78.721,46.511 78.721,46.624 78.892,46.795 78.892,46.839 78.916,46.863 78.916,46.958 79.116,47.158 R101.1@79.211,47.158
eMMC.SDMMC2_D1: U14.B16 U37.A4 | length 18.8
  Signal Layer 2 w0.12: v1(73.475,38.15) 73.731,38.406 73.731,39.504 74.235,40.008 74.235,41.558 73.926,41.867 73.926,42.046 74.039,42.158 74.266,42.158 74.797,41.628 75.936,41.628 76.363,42.054 76.363,42.725 75.37,43.718 75.37,43.886 76.688,45.203 76.935,45.203 78.202,43.937 78.7,43.937 79.653,44.89 79.653,45.997 79.103,46.547 79.103,46.681 78.775,47.01 78.775,47.18 79.249,47.655 v3@79.249,47.899
  other v1: 79.25,47.95
  other v3: 73.475,38.15 79.25,47.95
eMMC.SDMMC2_D2: U14.B15 U37.A5 | length 20
  Top Layer w0.09: U37.A5@79.225,48.45 U37.A5@79.25,48.475
  Top Layer w0.11: v1(78.9,48.45) U37.A5@79.225,48.45
  Signal Layer 2 w0.12: v1(72.975,38.15) 72.975,38.525 73.085,38.635 73.085,39.763 73.595,40.273 73.595,40.542 73.202,40.935 73.202,42.374 73.953,43.126 74.349,43.126 75.05,42.425 75.25,42.425 75.35,42.525 75.35,42.725 74.577,43.498 74.577,44.034 76.812,46.269 77.038,46.269 78.431,44.876 78.613,44.876 78.749,45.012 78.749,45.269 77.405,46.613 77.405,46.83 78.6,48.025 78.6,48.15 v1(78.9,48.45)
  other v3: 72.975,38.15 78.9,48.45
eMMC.SDMMC2_D3: U14.C16 U37.B2 | length 19.4
  Signal Layer 2 w0.12: v3(73.475,37.65) 73.835,37.65 74.371,38.185 74.371,39.239 74.875,39.743 74.875,40.701 75.156,40.982 76.683,40.982 77.781,42.081 77.781,42.367 76.406,43.742 76.406,43.966 76.585,44.145 76.804,44.145 78.228,42.72 78.495,42.72 81.6,45.825 81.6,46.025 80.675,46.95 v3@79.751,46.95
  other v1: 73.475,37.65 79.75,46.95
  other v3: 79.75,46.95
eMMC.SDMMC2_D4: U14.D15 U37.B3 | length 19.2
  Signal Layer 2 w0.075: v1(72.975,37.15) 73.224,37.399 73.224,37.752 73.373,37.901 73.651,37.901 73.775,38.025
  Signal Layer 2 w0.12: 73.774,38.024 74.051,38.301 74.051,39.371 74.555,39.876 74.555,40.855 75.003,41.303 76.528,41.303 77.256,42.031 77.256,42.331 75.883,43.704 75.883,43.942 76.66,44.719 76.865,44.719 78.283,43.301 78.528,43.301 80.336,45.109 80.336,45.862 79.424,46.774 79.424,47.126 v1(79.75,47.45)
  other v3: 72.975,37.15 79.75,47.45
eMMC.SDMMC2_D5: U14.F15 U37.B4 | length 19.7
  Top Layer w0.075: U14.F15@72.975,36.15 73.225,36.4 73.225,38.253 73.388,38.415 73.572,38.415 73.725,38.569 73.725,39.583
  Top Layer w0.11: 73.725,39.583 73.977,39.834 73.977,40.082 74.445,40.55 v3(75.325,40.55)
  Signal Layer 2 w0.12: v3(75.325,40.55) 76.8,40.55 82.525,46.275 82.525,46.675 82.4,46.8 81.625,46.8 81.45,46.975 81.45,47.75 81.276,47.924 79.776,47.924 v1(79.75,47.95)
  other v1: 75.325,40.55
  other v3: 79.75,47.95
eMMC.SDMMC2_D6: U14.F14 U37.B5 | length 18.6
  Top Layer w0.09: v1@78.7,49.338 v3(78.7,49.3) 78.9,49.1 78.9,48.937 79.144,48.693 79.507,48.693
  Top Layer w0.12: 79.507,48.693 U37.B5@79.75,48.45
  Signal Layer 1 w0.1: v3(78.7,49.3) v1(78.7,49.325)
  Signal Layer 2 w0.075: 72.2,40.312 72.385,40.127 72.385,37.913 72.226,37.753 72.226,37.547 72.298,37.474 72.298,36.327 v1(72.475,36.15)
  Signal Layer 2 w0.12: 72.2,40.312 72.2,43.003 72.343,43.146 72.946,43.146 73.105,43.305 73.105,44.211 73.287,44.393 73.793,44.393 73.978,44.578 73.978,45.013 74.14,45.175 74.575,45.175 v3(78.7,49.3)
  other v3: 72.475,36.15
eMMC.SDMMC2_D7: U14.C15 U37.B6 | length 21.5
  Top Layer w0.11: U37.B6@79.75,48.95 v3(80,48.7)
  Signal Layer 2 w0.075: v3@73.01,37.685 73.01,37.833 73.225,38.048 73.225,38.345 ; 78.925,47.85 78.925,47.855
  Signal Layer 2 w0.12: v1(72.975,37.65) v3@73.01,37.685 ; 73.225,38.345 73.4,38.519 73.4,39.626 73.915,40.141 73.915,40.675 73.555,41.035 73.555,42.275 73.883,42.603 74.398,42.603 75.043,41.958 75.678,41.958 75.821,42.101 75.821,42.762 74.943,43.64 74.943,43.92 76.772,45.749 76.972,45.749 78.355,44.366 78.666,44.366 79.125,44.825 79.125,45.53 78.025,46.63 78.025,46.955 78.925,47.855 78.925,48.05 79.584,48.709 79.991,48.709 v3(80,48.7)
  other v1: 80,48.7
  other v3: 72.975,37.65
